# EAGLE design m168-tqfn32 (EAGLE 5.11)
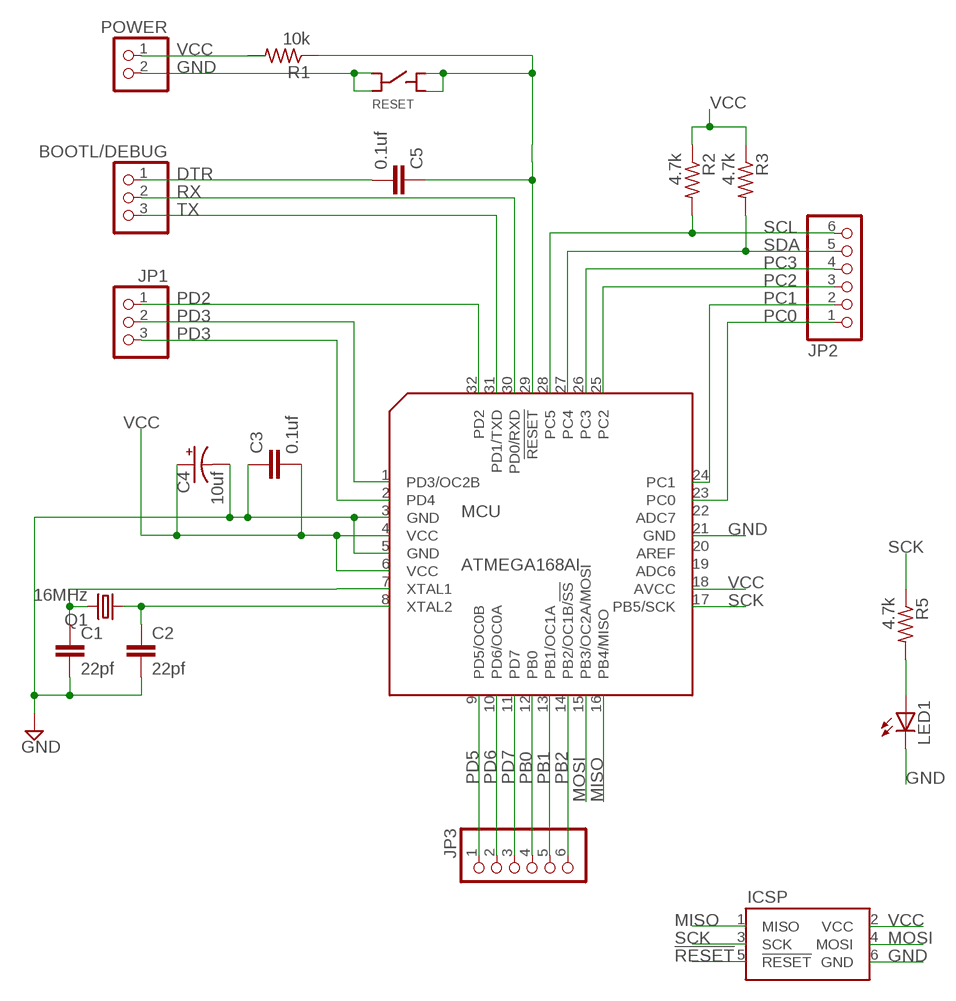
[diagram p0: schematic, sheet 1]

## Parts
BOOTL/DEBUG  PINHD-1X3  [1X03]
C1  22pf  C-EUC0805  [C0805]
C2  22pf  C-EUC0805  [C0805]
C3  0.1uf  C-EUC0805  [C0805]
C4  10uf  CPOL-USE2-4  [E2-4]
C5  0.1uf  C-EUC0805  [C0805]
ICSP  HEADER-AVR-PROG  [HEADER-AVR-PROG]
JP1  PINHD-1X3  [1X03]
JP2  PINHD-1X6  [1X06]
JP3  PINHD-1X6  [1X06]
LED1  LED5MM  [LED5MM]
MCU  ATMEGA168AI  [TQFP32-08]
POWER  PINHD-1X2  [1X02]
Q1  16MHz  CRYSTALHC49U-V  [HC49U-V]
R1  10k  R-US_R0805  [R0805]
R2  4.7k  R-US_R1206  [R1206]
R3  4.7k  R-US_R1206  [R1206]
R5  4.7k  R-US_R1206  [R1206]
RESET  SFE-PUSHBUTTON-SWITCH  [SFE-PUSHBUTTON-SWITCH]

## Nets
!RESET: C5.1 ICSP.5(!RESET) MCU.29(!RESET) R1.1 RESET.O@1(O) RESET.O@2(O)
DTR: BOOTL/DEBUG.1 C5.2
GND: C1.2 C2.2 C3.1 C4.- ICSP.6(GND) LED1.K(C) MCU.3(GND) MCU.5(GND) MCU.21(GND) POWER.2 RESET.C@1(C) RESET.C@2(C)
MISO: ICSP.1(MISO) MCU.16(PB4/MISO)
MOSI: ICSP.4(MOSI) MCU.15(PB3/OC2A/MOSI)
N$2: C2.1 MCU.8(XTAL2) Q1.1
N$3: C1.1 MCU.7(XTAL1) Q1.2
N$4: LED1.A R5.2
PB0: JP3.4 MCU.12(PB0)
PB1: JP3.5 MCU.13(PB1/OC1A)
PB2: JP3.6 MCU.14(PB2/OC1B/!SS)
PC0: JP2.1 MCU.23(PC0)
PC1: JP2.2 MCU.24(PC1)
PC2: JP2.3 MCU.25(PC2)
PC3: JP2.4 MCU.26(PC3)
PD2: JP1.1 MCU.32(PD2)
PD3: JP1.2 MCU.1(PD3/OC2B)
PD4: JP1.3 MCU.2(PD4)
PD5: JP3.1 MCU.9(PD5/OC0B)
PD6: JP3.2 MCU.10(PD6/OC0A)
PD7: JP3.3 MCU.11(PD7)
RX: BOOTL/DEBUG.2 MCU.30(PD0/RXD)
SCK: ICSP.3(SCK) MCU.17(PB5/SCK) R5.1
SCL: JP2.6 MCU.28(PC5) R2.2
SDA: JP2.5 MCU.27(PC4) R3.2
TX: BOOTL/DEBUG.3 MCU.31(PD1/TXD)
VCC: C3.2 C4.+ ICSP.2(VCC) MCU.4(VCC) MCU.6(VCC) MCU.18(AVCC) POWER.1 R1.2 R2.1 R3.1
Unconnected: MCU.19(ADC6) MCU.20(AREF) MCU.22(ADC7)

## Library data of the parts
BOOTL/DEBUG JP1 = pinhead:PINHD-1X3: PIN HEADER
C1-C3 C5 = rcl:C-EU: CAPACITOR, European symbol
C4 = rcl:CPOL-US: POLARIZED CAPACITOR, American symbol
ICSP = trl:HEADER-AVR-PROG
JP2 JP3 = pinhead:PINHD-1X6: PIN HEADER
LED1 = led:LED: LED
MCU = trl:ATMEGA168
POWER = pinhead:PINHD-1X2: PIN HEADER
Q1 = crystal:CRYSTAL: CRYSTAL; OC_FARNELL: 1666969; OC_NEWARK: unknown
R1-R3 R5 = resistor:R-US_: RESISTOR, American symbol
RESET = trl:SFE-PUSHBUTTON-SWITCH

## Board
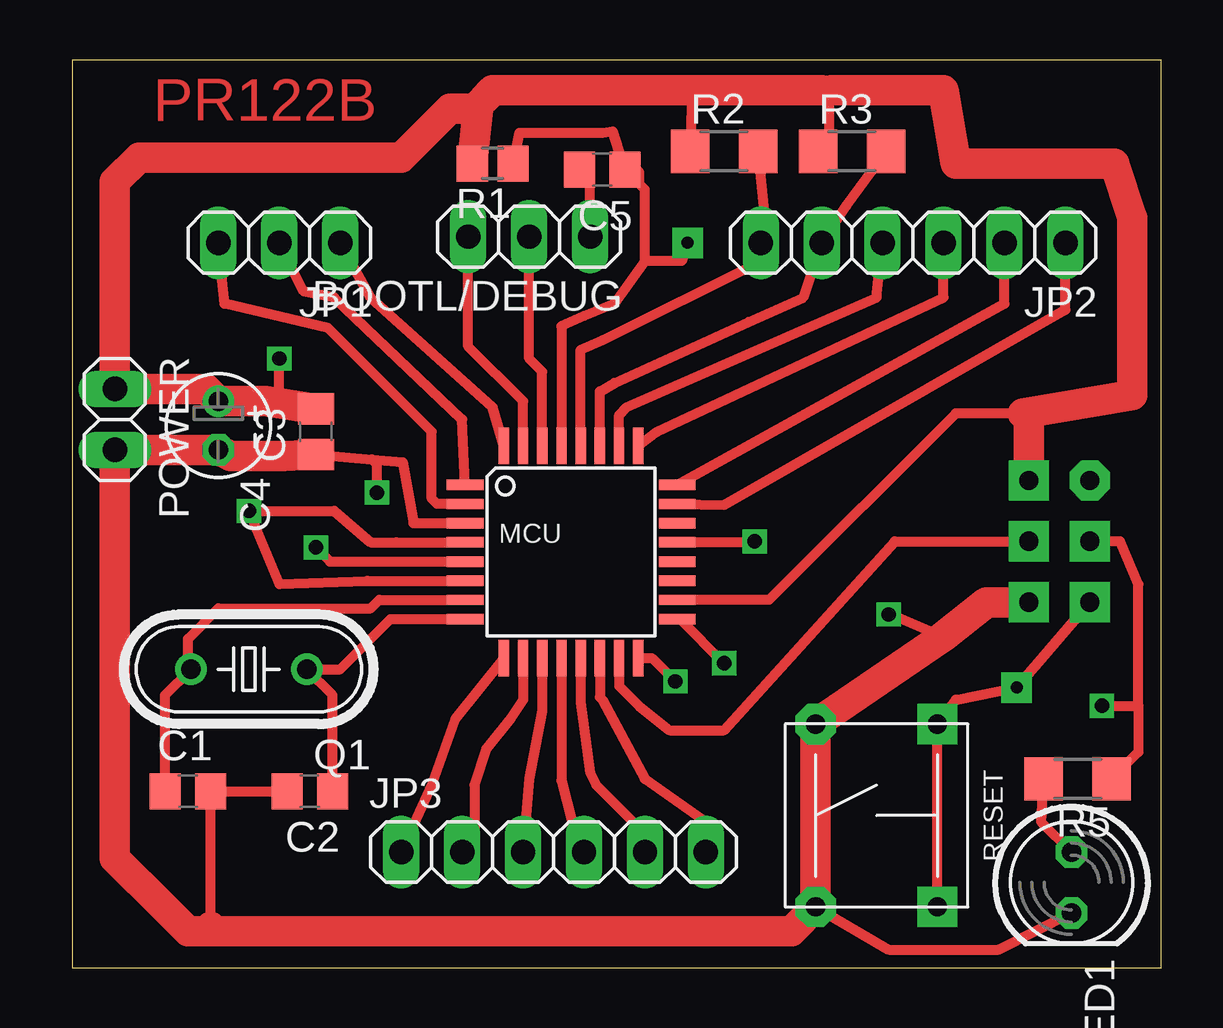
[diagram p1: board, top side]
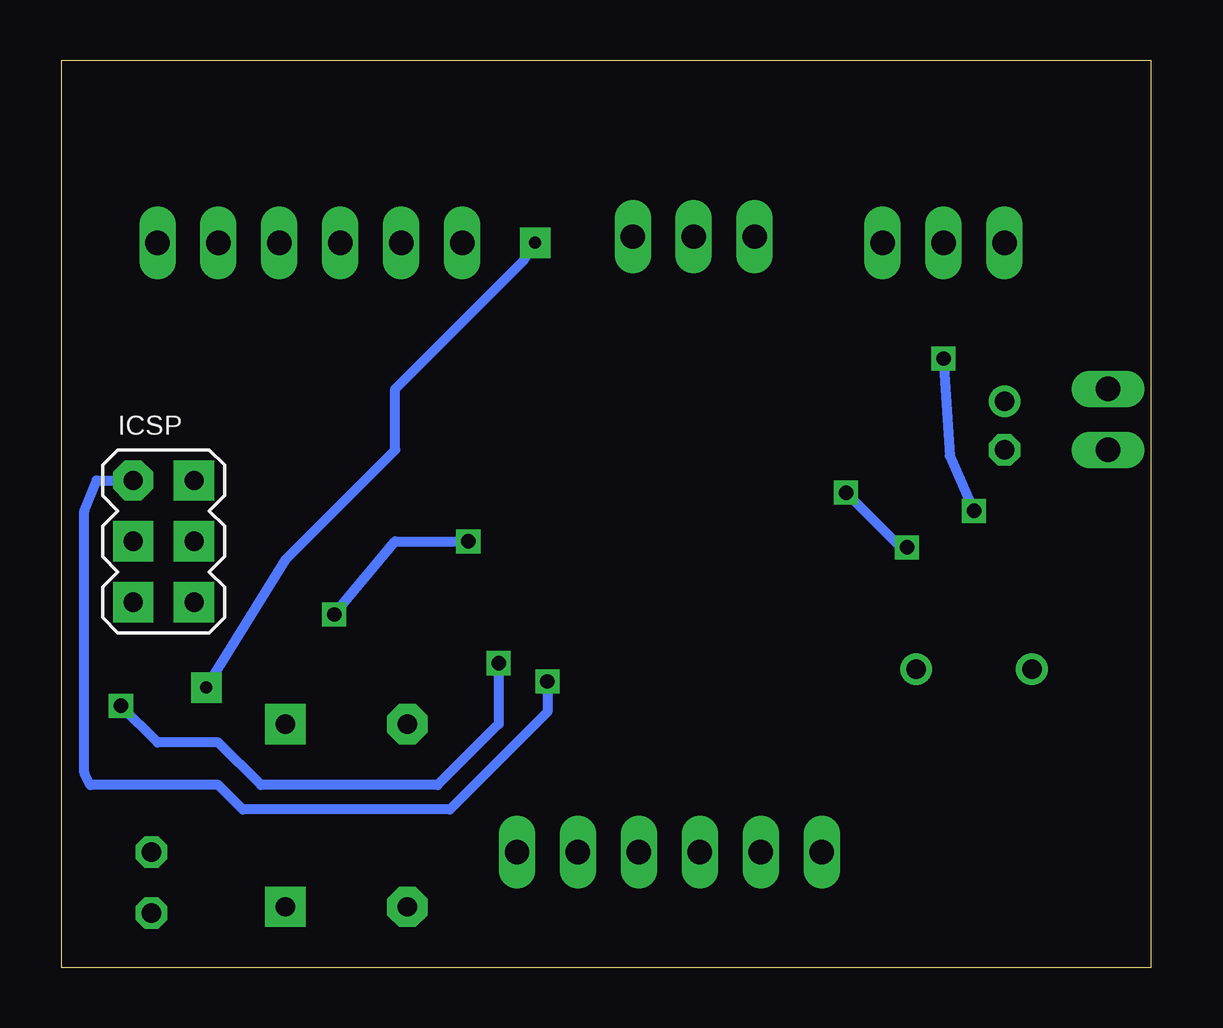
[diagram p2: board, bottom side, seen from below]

Size 45.39 x 37.84 mm. Coordinates in mm from the lower left corner, seen from the top.
Outline: 0,0 45.39,0 45.39,37.84 0,37.84 0,0
Copper layers (1*16): Top 0.035mm / dielectric 1.5mm / Bottom 0.035mm
Design rules "default": minimum track width 10mil, minimum drill 24mil, track to track 8mil, track to pad 8mil, pad to pad 8mil, via to via 8mil, smd to smd 8mil, copper to edge 40mil, drill to drill 8mil, minimum pad ring 10mil, minimum via ring 8mil, stop-mask expansion 4mil, vias tented up to drill 0mil, thermal gap 10mil

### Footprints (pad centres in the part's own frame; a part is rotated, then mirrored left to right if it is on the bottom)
1X03 = drill 1.016 long: 1 -2.54,0; 2 0,0; 3 2.54,0
C0805 = smd 1.3 x 1.5: 1 -0.95,0; 2 0.95,0
E2-4 = drill 0.813 pad 1.27 round: + -1.016,0 | drill 0.813 pad 1.27 octagon: - 1.016,0
HEADER-AVR-PROG = drill 0.8 pad 1.676 octagon: 1 -2.54,-1.27 | drill 0.8 pad 1.676 square: 2 -2.54,1.27; 3 0,-1.27; 4 0,1.27; 5 2.54,-1.27; 6 2.54,1.27
1X06 = drill 1.016 long: 1 -6.35,0; 2 -3.81,0; 3 -1.27,0; 4 1.27,0; 5 3.81,0; 6 6.35,0
LED5MM = drill 0.813 octagon: A -1.27,0; K 1.27,0
TQFP32-08 = smd 1.524 x 0.432: 1 -3.69,2.61; 2 -3.69,1.81; 3 -3.69,1.01; 4 -3.69,0.21; 5 -3.69,-0.59; 6 -3.69,-1.39; 7 -3.69,-2.19; 8 -3.69,-2.99; 17 5.15,-2.99; 18 5.15,-2.19; 19 5.15,-1.39; 20 5.15,-0.59; 21 5.15,0.21; 22 5.15,1.01; 23 5.15,1.81; 24 5.15,2.61 | smd 0.432 x 1.524: 9 -2.07,-4.61; 10 -1.27,-4.61; 11 -0.47,-4.61; 12 0.33,-4.61; 13 1.13,-4.61; 14 1.93,-4.61; 15 2.73,-4.61; 16 3.53,-4.61; 25 3.53,4.23; 26 2.73,4.23; 27 1.93,4.23; 28 1.13,4.23; 29 0.33,4.23; 30 -0.47,4.23; 31 -1.27,4.23; 32 -2.07,4.23
1X02 = drill 1.016 long: 1 -1.27,0; 2 1.27,0
HC49U-V = drill 0.813 round: 1 -2.413,0; 2 2.413,0
R0805 = smd 1.3 x 1.5: 1 -0.85,0; 2 0.85,0
R1206 = smd 1.6 x 1.803: 1 -1.422,0; 2 1.422,0
SFE-PUSHBUTTON-SWITCH = drill 0.8 pad 1.676 octagon: C@1 -3.81,-2.54; C@2 3.81,-2.54 | drill 0.8 pad 1.676 square: O@1 -3.81,2.54; O@2 3.81,2.54

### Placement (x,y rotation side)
BOOTL/DEBUG  19.05,30.48 180 top
C1  4.83,7.37 0 top
C2  9.91,7.37 180 top
C3  10.16,22.35 90 top
C4  6.1,22.61 270 top
C5  22.1,33.27 180 top
ICSP  41.15,17.78 270 bottom
JP1  8.64,30.23 180 top
JP2  35.05,30.23 180 top
JP3  20.07,4.83 0 top
LED1  41.66,3.56 270 top
MCU  20.07,17.53 0 top
POWER  1.78,22.86 270 top
Q1  7.37,12.45 180 top
R1  17.53,33.53 180 top
R2  27.18,34.04 0 top
R3  32.51,34.04 0 top
R5  41.91,7.87 180 top
RESET  33.53,6.35 270 top

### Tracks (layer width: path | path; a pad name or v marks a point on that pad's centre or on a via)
!RESET  (via drill 0.5 pad 1.27)
  Top 0.406: MCU.29 20.4,26.75 21.34,27.18 22.61,27.69 23.88,29.46 | 23.62,32.77 23.62,33.21 C5.1 | C5.1 22.54,34.86 22.1,34.8 18.63,34.8 R1.1 | ICSP.5 v39.37,11.68 36.83,11.18 RESET.O@1 RESET.O@2 | 23.88,29.46 23.88,32.45 C5.1 | 23.88,29.46 25.4,29.46 v25.65,30.23
  Bottom 0.406: v39.37,11.68 36.07,17.02 31.5,21.59 31.5,24.13 26.16,29.46 v25.65,30.23
DTR
  Top 0.406: 21.34,33.72 C5.2 21.59,32.83 BOOTL/DEBUG.1
GND  (via drill 0.6)
  Top 0.406: MCU.3 15.5,18.54 14.22,18.54 13.78,21.08 12.5,21.2 | C2.2 C1.2 5.78,1.71 | RESET.C@2 34.04,0.76 38.61,0.76 LED1.K | C3.1 12.5,21.2 | MCU.21 28.4,17.74 v28.45,17.78 | v34.04,14.73 34.54,14.55 36.3,13.8 | MCU.5 10.75,16.94 v10.16,17.53 | v12.7,19.81 12.7,21 12.5,21.2
  Top 1.27: ICSP.6 38.1,15.24 36.3,13.8 RESET.C@1 RESET.C@2 29.97,1.52 5.59,1.52 | 5.59,1.52 4.83,1.52 3.81,2.54 1.78,4.57 POWER.2 C4.- 6.6,21.34 7.11,21.34 8.82,21.34 C3.1 | 5.78,1.71 5.59,1.52
  Bottom 0.406: v28.45,17.78 31.5,17.78 v34.04,14.73 | v10.16,17.53 10.41,17.53 v12.7,19.81
MISO  (via drill 0.6)
  Top 0.406: MCU.16 24.17,12.92 v25.15,11.94
  Bottom 0.406: v25.15,11.94 25.15,10.67 29.21,6.6 37.85,6.6 38.86,7.62 44.2,7.62 44.45,8.13 44.45,19.05 43.94,20.32 ICSP.1
MOSI
  Top 0.406: MCU.15 22.8,11.75 23.62,10.92 24.89,9.91 27.18,9.91 34.29,17.78 ICSP.4
N$2
  Top 0.406: MCU.8 13.27,14.54 12.45,13.72 11.18,12.45 Q1.1 10.86,11.37 C2.1
N$3
  Top 0.406: MCU.7 12.8,15.34 12.45,14.99 6.1,14.99 4.83,13.72 4.83,12.57 Q1.2 3.88,11.37 C1.1
N$4
  Top 0.406: R5.2 40.39,6.1 LED1.A
PB0
  Top 0.406: MCU.12 20.4,7.8 20.83,6.1 20.83,5.33 JP3.4
PB1
  Top 0.406: MCU.13 21.2,11.06 21.59,8.13 21.84,7.62 23.11,6.35 24.13,5.33 24.13,5.08 JP3.5
PB2
  Top 0.406: MCU.14 22,11.28 22.1,11.18 23.88,7.87 26.42,6.1 JP3.6
PC0
  Top 0.406: MCU.23 27.18,19.3 41.4,27.43 JP2.1
PC1
  Top 0.406: MCU.24 38.86,27.69 JP2.2
PC2
  Top 0.406: MCU.25 24.38,22.35 36.32,27.94 JP2.3
PC3
  Top 0.406: MCU.26 22.8,23.05 23.11,23.37 33.53,27.94 JP2.4
PD2
  Top 0.406: MCU.32 17.53,23.37 12.45,27.94 JP1.1
PD3
  Top 0.406: MCU.1 16.26,22.86 10.92,27.94 9.65,28.19 JP1.2
PD4
  Top 0.406: MCU.2 15.21,19.34 14.99,19.56 14.99,22.35 10.67,26.67 6.35,27.69 JP1.3
PD5
  Top 0.406: MCU.9 15.96,10.38 14.99,7.62 JP3.1
PD6
  Top 0.406: MCU.10 18.8,11.18 18.29,10.41 17.27,9.14 16.76,7.62 16.76,5.33 JP3.2
PD7
  Top 0.406: MCU.11 19.6,10.71 19.05,7.87 JP3.3
RX
  Top 0.406: MCU.30 19.6,24.85 19.05,25.4 BOOTL/DEBUG.2
SCK  (via drill 0.6)
  Top 0.406: MCU.17 25.34,14.54 v27.18,12.7 | ICSP.3 43.69,17.78 44.45,16 44.45,10.92 | 44.45,10.92 44.45,8.99 R5.1 | v42.93,10.92 44.45,10.92
  Bottom 0.406: v27.18,12.7 27.18,10.16 29.72,7.62 37.08,7.62 38.86,9.4 41.4,9.4 v42.93,10.92
SCL
  Top 0.406: MCU.28 21.2,25.77 22.1,26.16 28.7,29.46 JP2.6 28.96,30.48 R2.2
SDA
  Top 0.406: MCU.27 22,24.03 22.61,24.38 28.19,26.92 30.48,27.94 JP2.5 32.26,31.75 R3.2
TX
  Top 0.406: MCU.31 18.8,23.62 16.51,25.91 BOOTL/DEBUG.3
VCC  (via drill 0.6)
  Top 0.406: 24.74,36.58 25.84,36.43 | 25.84,36.43 R2.1 | 31.24,36.58 31.34,36.47 31.55,36.47 | 25.84,36.43 24.97,36.58 | 31.55,36.47 31.65,36.58 | 31.55,36.47 31.55,34.24 R3.1 | MCU.18 29.05,15.34 36.83,23.11 39.62,23.11 | MCU.6 12.31,16.14 8.64,16 v7.37,19.05 10.92,19.05 12.45,17.74 13.51,17.74 MCU.4 | v8.64,25.4 8.64,23.62 9.91,23.62 10.23,23.37 C3.2
  Top 1.27: R1.2 16.93,35.98 17.14,36.2 | 17.14,36.2 17.53,36.58 24.74,36.58 | 31.65,36.58 36.32,36.58 36.83,33.53 43.43,33.53 44.2,31.24 44.2,23.88 39.62,23.11 39.88,23.11 ICSP.2 | 24.97,36.58 31.24,36.58 | 17.14,36.2 16.76,35.81 15.75,35.81 13.72,33.78 2.79,33.78 1.78,32.77 POWER.1 5.59,24.13 C4.+ 8.06,23.62 C3.2
  Bottom 0.406: v7.37,19.05 8.38,21.34 v8.64,25.4

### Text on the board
Top: PR122B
